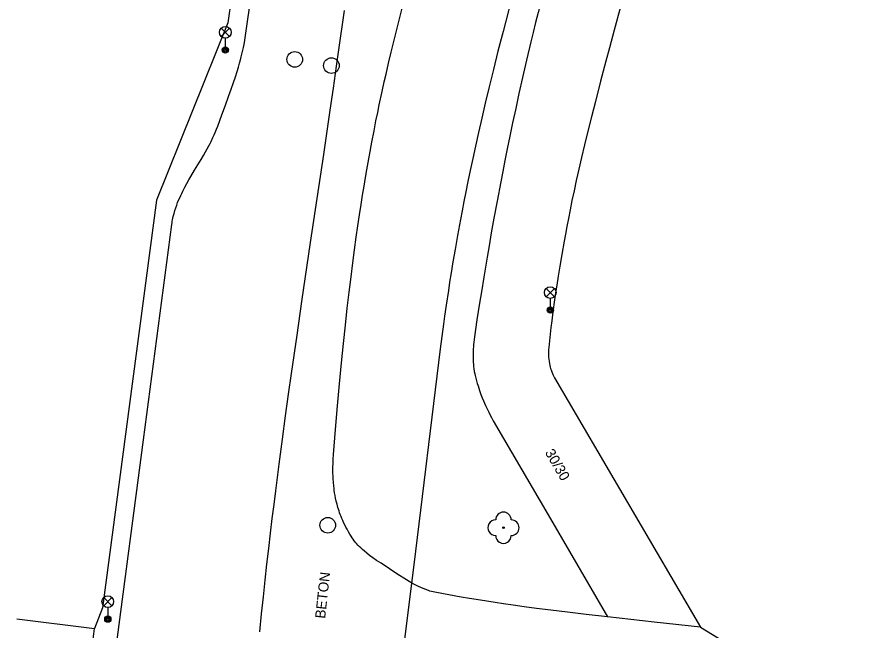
# Model space of a CAD drawing. Extents: x -541281 to -539153, y -1183881 to -1182141.
# Drawn here: x -539888.4 to -539834, y -1183350 to -1183310.7 of the extents above; entities that cross this region are included whole.
import ezdxf

# ---------------------------------------------------------------- set-up
doc = ezdxf.new("R2010")
doc.units = 0
for name, color, linetype in [('Vrstva 10', 7, 'Continuous'), ('Vrstva 11', 7, 'Continuous'), ('Vrstva 13', 7, 'Continuous'), ('Vrstva 22', 7, 'Continuous'), ('Vrstva 27', 7, 'Continuous'), ('Vrstva 33', 7, 'Continuous'), ('Vrstva 40', 7, 'Continuous'), ('Vrstva 5', 7, 'Continuous'), ('Vrstva 7', 7, 'Continuous')]:
    doc.layers.add(name, color=color, linetype=linetype)

msp = doc.modelspace()

# ---------------------------------------------------------------- linework, layer by layer
at = {"layer": 'Vrstva 10'}
for p, q in [((-539869.559, -1183325.144), (-539868.719, -1183319.488)), ((-539880.275, -1183337.78), (-539878.46, -1183323.99)), ((-539870.117, -1183328.915), (-539869.559, -1183325.144)), ((-539870.432, -1183331.07), (-539870.117, -1183328.915)), ((-539853.92, -1183333.82), (-539849.245, -1183341.81)), ((-539882.09, -1183351.57), (-539880.275, -1183337.78)), ((-539871.797, -1183341.049), (-539871.578, -1183339.345))]:
    msp.add_line(p, q, dxfattribs=at)
for points in [[(-539874.497, -1183314.881), (-539874.374, -1183314.511), (-539874.271, -1183314.186), (-539874.185, -1183313.9), (-539874.114, -1183313.65), (-539874.054, -1183313.43), (-539874.004, -1183313.237), (-539873.923, -1183312.898), (-539873.867, -1183312.643), (-539873.828, -1183312.45), (-539873.776, -1183312.161), (-539873.73, -1183311.87), (-539873.345, -1183309.183), (-539872.99, -1183306.663)], [(-539849.461, -1183309.17), (-539849.697, -1183310.027), (-539850.105, -1183311.532), (-539850.408, -1183312.665), (-539850.635, -1183313.517), (-539850.973, -1183314.8), (-539851.311, -1183316.089), (-539851.565, -1183317.075), (-539851.797, -1183317.999)], [(-539868.719, -1183319.488), (-539868.305, -1183316.659), (-539868.101, -1183315.245), (-539867.9, -1183313.83), (-539867.644, -1183312.045), (-539867.516, -1183311.153), (-539867.39, -1183310.26)], [(-539878.46, -1183323.99), (-539878.445, -1183323.882), (-539878.427, -1183323.777), (-539878.408, -1183323.674), (-539878.365, -1183323.473), (-539878.316, -1183323.28), (-539878.263, -1183323.095), (-539878.206, -1183322.918), (-539878.146, -1183322.747), (-539878.083, -1183322.583), (-539878.019, -1183322.426), (-539877.954, -1183322.274), (-539877.888, -1183322.128), (-539877.821, -1183321.987), (-539877.754, -1183321.851), (-539877.62, -1183321.589), (-539877.488, -1183321.346), (-539877.36, -1183321.119), (-539877.237, -1183320.906), (-539877.002, -1183320.51), (-539876.586, -1183319.816), (-539876.432, -1183319.555), (-539876.299, -1183319.325), (-539876.186, -1183319.123), (-539876.09, -1183318.946), (-539876.008, -1183318.79), (-539875.938, -1183318.653), (-539875.82, -1183318.411), (-539875.736, -1183318.228), (-539875.675, -1183318.09), (-539875.59, -1183317.881), (-539875.51, -1183317.67), (-539875.249, -1183316.956), (-539875.017, -1183316.331), (-539874.815, -1183315.784), (-539874.643, -1183315.303), (-539874.497, -1183314.881)], [(-539851.797, -1183317.999), (-539852.007, -1183318.866), (-539852.199, -1183319.678)], [(-539852.199, -1183319.678), (-539852.374, -1183320.44), (-539852.533, -1183321.154), (-539852.678, -1183321.824), (-539852.81, -1183322.452), (-539852.93, -1183323.041), (-539853.04, -1183323.592), (-539853.14, -1183324.11), (-539853.232, -1183324.595), (-539853.316, -1183325.05), (-539853.467, -1183325.902), (-539853.593, -1183326.648), (-539853.698, -1183327.301), (-539853.787, -1183327.872), (-539853.861, -1183328.372), (-539853.924, -1183328.809)], [(-539853.924, -1183328.809), (-539854.028, -1183329.575), (-539854.102, -1183330.149)], [(-539854.102, -1183330.149), (-539854.155, -1183330.579), (-539854.23, -1183331.224), (-539854.3, -1183331.87), (-539854.311, -1183331.993), (-539854.317, -1183332.109), (-539854.319, -1183332.219), (-539854.318, -1183332.323), (-539854.314, -1183332.421), (-539854.308, -1183332.513), (-539854.3, -1183332.599), (-539854.28, -1183332.76), (-539854.256, -1183332.9), (-539854.23, -1183333.022), (-539854.204, -1183333.127), (-539854.178, -1183333.218), (-539854.153, -1183333.297), (-539854.105, -1183333.433), (-539854.064, -1183333.533), (-539854.031, -1183333.607), (-539853.978, -1183333.715), (-539853.92, -1183333.82)], [(-539871.578, -1183339.345), (-539871.367, -1183337.748), (-539871.164, -1183336.252), (-539870.97, -1183334.849), (-539870.785, -1183333.534), (-539870.432, -1183331.07)], [(-539872.811, -1183350.082), (-539872.699, -1183348.945), (-539872.586, -1183347.843), (-539872.472, -1183346.777), (-539872.358, -1183345.744), (-539872.244, -1183344.744), (-539872.131, -1183343.775), (-539872.018, -1183342.837), (-539871.907, -1183341.929), (-539871.797, -1183341.049)], [(-539849.245, -1183341.81), (-539844.57, -1183349.8), (-539834.025, -1183356.252)]]:
    msp.add_lwpolyline(points, dxfattribs=at)
at = {"layer": 'Vrstva 11'}
for p, q in [((-539857.964, -1183336.359), (-539857.85, -1183336.56)), ((-539857.85, -1183336.56), (-539854.19, -1183342.85)), ((-539854.19, -1183342.85), (-539850.53, -1183349.14))]:
    msp.add_line(p, q, dxfattribs=at)
for points in [[(-539854.044, -1183306.849), (-539854.249, -1183307.603), (-539854.445, -1183308.334), (-539854.631, -1183309.043), (-539854.808, -1183309.73), (-539854.977, -1183310.396), (-539855.139, -1183311.042), (-539855.293, -1183311.667), (-539855.44, -1183312.273), (-539855.719, -1183313.449), (-539855.973, -1183314.552), (-539856.206, -1183315.587), (-539856.418, -1183316.557)], [(-539865.79, -1183319.53), (-539865.637, -1183318.703), (-539865.498, -1183317.98), (-539865.373, -1183317.348), (-539865.261, -1183316.794), (-539865.16, -1183316.311), (-539864.978, -1183315.464), (-539864.837, -1183314.83), (-539864.729, -1183314.355), (-539864.562, -1183313.642), (-539864.39, -1183312.93), (-539864.119, -1183311.833), (-539863.863, -1183310.808), (-539863.622, -1183309.851)], [(-539856.418, -1183316.557), (-539856.613, -1183317.468), (-539856.792, -1183318.322), (-539856.956, -1183319.123), (-539857.107, -1183319.875), (-539857.246, -1183320.579), (-539857.374, -1183321.24), (-539857.609, -1183322.48), (-539857.808, -1183323.566), (-539857.978, -1183324.516), (-539858.123, -1183325.348), (-539858.248, -1183326.077)], [(-539866.972, -1183327.347), (-539866.857, -1183326.444), (-539866.744, -1183325.596), (-539866.635, -1183324.802), (-539866.528, -1183324.058), (-539866.424, -1183323.36), (-539866.324, -1183322.706), (-539866.227, -1183322.093), (-539866.133, -1183321.519), (-539866.044, -1183320.98), (-539865.957, -1183320.476), (-539865.79, -1183319.53)], [(-539858.248, -1183326.077), (-539858.461, -1183327.352), (-539858.616, -1183328.308), (-539858.73, -1183329.026), (-539858.897, -1183330.103), (-539859.06, -1183331.18), (-539859.084, -1183331.354), (-539859.104, -1183331.518), (-539859.119, -1183331.673), (-539859.131, -1183331.818), (-539859.14, -1183331.955), (-539859.146, -1183332.083), (-539859.15, -1183332.204), (-539859.152, -1183332.431), (-539859.147, -1183332.629), (-539859.138, -1183332.802), (-539859.126, -1183332.954), (-539859.113, -1183333.086), (-539859.098, -1183333.202), (-539859.068, -1183333.403), (-539859.04, -1183333.554), (-539859.016, -1183333.666), (-539858.976, -1183333.834), (-539858.93, -1183334), (-539858.879, -1183334.169), (-539858.829, -1183334.326), (-539858.732, -1183334.618), (-539858.641, -1183334.871), (-539858.557, -1183335.09), (-539858.481, -1183335.279), (-539858.411, -1183335.444), (-539858.348, -1183335.587), (-539858.233, -1183335.835)], [(-539867.21, -1183329.34), (-539867.09, -1183328.312), (-539866.972, -1183327.347)], [(-539868.09, -1183338.73), (-539867.96, -1183337.118), (-539867.832, -1183335.605), (-539867.705, -1183334.187), (-539867.579, -1183332.856), (-539867.455, -1183331.608), (-539867.331, -1183330.438), (-539867.21, -1183329.34)], [(-539858.233, -1183335.835), (-539858.143, -1183336.019), (-539858.073, -1183336.156), (-539857.964, -1183336.359)], [(-539864.293, -1183346.193), (-539864.72, -1183345.91), (-539864.888, -1183345.801), (-539865.044, -1183345.7), (-539865.33, -1183345.512), (-539865.574, -1183345.344), (-539865.781, -1183345.193), (-539865.959, -1183345.056), (-539866.11, -1183344.931), (-539866.239, -1183344.816), (-539866.349, -1183344.711), (-539866.444, -1183344.616), (-539866.525, -1183344.53), (-539866.595, -1183344.452), (-539866.655, -1183344.382), (-539866.759, -1183344.254), (-539866.834, -1183344.154), (-539866.889, -1183344.076), (-539866.971, -1183343.956), (-539867.05, -1183343.83), (-539867.143, -1183343.673), (-539867.228, -1183343.521), (-539867.306, -1183343.373), (-539867.378, -1183343.229), (-539867.444, -1183343.09), (-539867.504, -1183342.956), (-539867.56, -1183342.825), (-539867.611, -1183342.698), (-539867.657, -1183342.575), (-539867.7, -1183342.456), (-539867.739, -1183342.341), (-539867.809, -1183342.117), (-539867.868, -1183341.906), (-539867.917, -1183341.709), (-539867.958, -1183341.524), (-539867.992, -1183341.35), (-539868.02, -1183341.187), (-539868.043, -1183341.034), (-539868.062, -1183340.891), (-539868.078, -1183340.756), (-539868.101, -1183340.504), (-539868.116, -1183340.282), (-539868.125, -1183340.089), (-539868.129, -1183339.919), (-539868.131, -1183339.771), (-539868.129, -1183339.511), (-539868.124, -1183339.316), (-539868.11, -1183339.023), (-539868.09, -1183338.73)], [(-539863.587, -1183346.658), (-539863.87, -1183346.475), (-539864.293, -1183346.193)], [(-539854.156, -1183348.709), (-539855.075, -1183348.589), (-539855.878, -1183348.48), (-539856.58, -1183348.38), (-539857.194, -1183348.291), (-539857.732, -1183348.21), (-539858.672, -1183348.064), (-539859.377, -1183347.949), (-539859.905, -1183347.861), (-539860.698, -1183347.723), (-539861.49, -1183347.58), (-539861.602, -1183347.558), (-539861.709, -1183347.533), (-539861.811, -1183347.507), (-539861.91, -1183347.479), (-539862.004, -1183347.449), (-539862.185, -1183347.387), (-539862.352, -1183347.322), (-539862.507, -1183347.255), (-539862.651, -1183347.189), (-539862.784, -1183347.123), (-539862.908, -1183347.058), (-539863.024, -1183346.996), (-539863.238, -1183346.872), (-539863.425, -1183346.76), (-539863.587, -1183346.658)], [(-539844.57, -1183349.8), (-539847.55, -1183349.47), (-539850.53, -1183349.14), (-539851.905, -1183348.984), (-539853.106, -1183348.841), (-539854.156, -1183348.709)]]:
    msp.add_lwpolyline(points, dxfattribs=at)
at = {"layer": 'Vrstva 13'}
for p, q in [((-539861.25, -1183331.96), (-539862.95, -1183345.795)), ((-539862.95, -1183345.795), (-539864.65, -1183359.63))]:
    msp.add_line(p, q, dxfattribs=at)
for points in [[(-539854.621, -1183302.298), (-539854.891, -1183303.214), (-539855.151, -1183304.102), (-539855.401, -1183304.963), (-539855.64, -1183305.797), (-539855.869, -1183306.605), (-539856.089, -1183307.388), (-539856.3, -1183308.148), (-539856.502, -1183308.883), (-539856.696, -1183309.597), (-539856.881, -1183310.288), (-539857.058, -1183310.958), (-539857.228, -1183311.607)], [(-539857.228, -1183311.607), (-539857.552, -1183312.867), (-539857.849, -1183314.048), (-539858.12, -1183315.157), (-539858.368, -1183316.198), (-539858.596, -1183317.175), (-539858.804, -1183318.091), (-539858.995, -1183318.951), (-539859.17, -1183319.758), (-539859.33, -1183320.515), (-539859.477, -1183321.226)], [(-539859.477, -1183321.226), (-539859.611, -1183321.892), (-539859.735, -1183322.517)], [(-539859.735, -1183322.517), (-539859.849, -1183323.104), (-539859.953, -1183323.655), (-539860.143, -1183324.688), (-539860.303, -1183325.593), (-539860.438, -1183326.386), (-539860.553, -1183327.08), (-539860.65, -1183327.688), (-539860.733, -1183328.221), (-539860.872, -1183329.154), (-539860.973, -1183329.854), (-539861.045, -1183330.38), (-539861.15, -1183331.17), (-539861.25, -1183331.96)]]:
    msp.add_lwpolyline(points, dxfattribs=at)
at = {"layer": 'Vrstva 22'}
msp.add_circle((-539857.2, -1183343.42), 0.05, dxfattribs=at)
for centre, start, end in [((-539857.2, -1183342.92), 359.9997, 179.9997), ((-539857.7, -1183343.42), 89.9997, 269.9997), ((-539856.7, -1183343.42), 269.9997, 89.9997), ((-539857.2, -1183343.92), 179.9997, 359.9997)]:
    msp.add_arc(centre, 0.5, start, end, dxfattribs=at)
at = {"layer": 'Vrstva 27'}
for centre in [(-539870.58, -1183313.4), (-539868.228, -1183313.799), (-539868.46, -1183343.26)]:
    msp.add_circle(centre, 0.5, dxfattribs=at)
at = {"layer": 'Vrstva 33'}
for p, q in [((-539875.295, -1183311.93), (-539874.765, -1183311.4)), ((-539875.295, -1183311.4), (-539874.765, -1183311.93)), ((-539875.03, -1183312.04), (-539875.03, -1183312.79)), ((-539854.465, -1183328.61), (-539853.935, -1183328.08)), ((-539854.465, -1183328.08), (-539853.935, -1183328.61)), ((-539854.2, -1183328.72), (-539854.2, -1183329.47)), ((-539882.825, -1183348.42), (-539882.295, -1183347.89)), ((-539882.825, -1183347.89), (-539882.295, -1183348.42)), ((-539882.56, -1183348.53), (-539882.56, -1183349.28))]:
    msp.add_line(p, q, dxfattribs=at)
for centre, radius in [((-539875.03, -1183311.665), 0.375), ((-539875.03, -1183312.79), 0.2), ((-539875.03, -1183312.79), 0.145), ((-539875.03, -1183312.79), 0.0876), ((-539854.2, -1183328.345), 0.375), ((-539854.2, -1183329.47), 0.2), ((-539854.2, -1183329.47), 0.145), ((-539854.2, -1183329.47), 0.0876), ((-539882.56, -1183348.155), 0.375), ((-539882.56, -1183349.28), 0.2), ((-539882.56, -1183349.28), 0.145), ((-539882.56, -1183349.28), 0.0876)]:
    msp.add_circle(centre, radius, dxfattribs=at)
at = {"layer": 'Vrstva 5'}
for p in [(-539888.383, -1183349.266), (-539884.21, -1183356.36)]:
    msp.add_line(p, (-539883.42, -1183349.87), dxfattribs=at)
at = {"layer": 'Vrstva 7'}
for p, q in [((-539870.19, -1183277.92), (-539874.87, -1183311.05)), ((-539874.87, -1183311.05), (-539879.44, -1183322.42)), ((-539879.44, -1183322.42), (-539882.89, -1183348.55)), ((-539882.89, -1183348.55), (-539883.42, -1183349.87))]:
    msp.add_line(p, q, dxfattribs=at)

# ---------------------------------------------------------------- texts
at = {"layer": 'Vrstva 40'}
for s, rotation, p in [('30/30', 300.1941, (-539854.564, -1183338.597)), ('BETON', 83.7617, (-539868.633, -1183349.267))]:
    msp.add_text(s, height=0.65, rotation=rotation, dxfattribs=at).set_placement(p)

doc.saveas('drawing.dxf')
